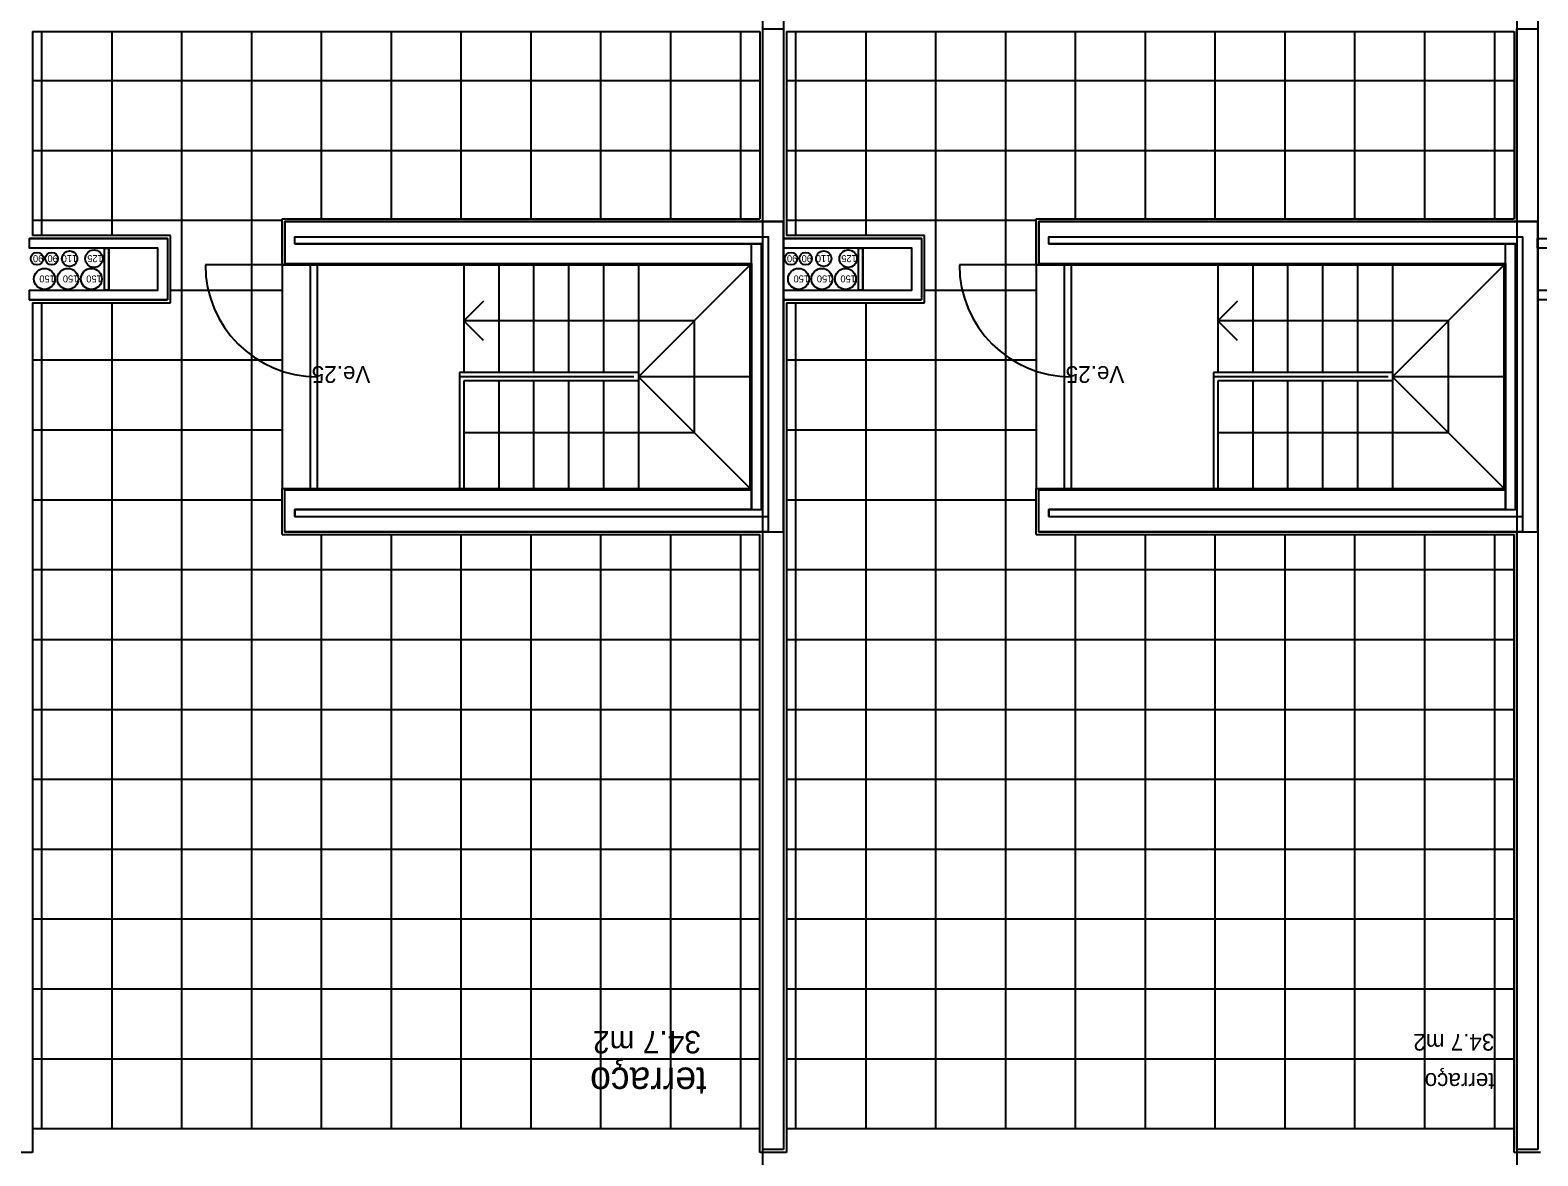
# Model space of a CAD drawing. Extents: x 1278 to 1356, y -253.7 to -224.
# Drawn here: x 1324.04 to 1334.83, y -246.8 to -238.74 of the extents above; entities that cross this region are included whole.
import ezdxf

# ---------------------------------------------------------------- set-up
doc = ezdxf.new("R2010")
doc.units = 0
for name, color, linetype in [('corte', 7, 'Continuous'), ('estereoctomias', 7, 'Continuous'), ('estrutura-eixos', 7, 'Continuous'), ('Level 1', 7, 'Continuous'), ('Level 13', 7, 'Continuous'), ('Level 2', 7, 'Continuous'), ('Level 21', 7, 'Continuous'), ('Level 40', 7, 'Continuous'), ('Level 41', 7, 'Continuous'), ('Level 60', 7, 'Continuous'), ('revestimentos', 7, 'Continuous')]:
    doc.layers.add(name, color=color, linetype=linetype)

msp = doc.modelspace()

# ---------------------------------------------------------------- linework, layer by layer
at = {"layer": 'corte'}
for p, q in [((1325.022, -240.234), (1324.034, -240.234)), ((1325.02, -240.234), (1325.02, -240.674)), ((1325.932, -240.224), (1329.322, -240.224)), ((1325.932, -240.274), (1325.932, -240.224)), ((1329.322, -240.224), (1329.322, -242.224)), ((1330.42, -240.234), (1329.432, -240.234)), ((1330.418, -240.234), (1330.418, -240.674)), ((1331.33, -240.224), (1334.721, -240.224)), ((1331.33, -240.274), (1331.33, -240.224)), ((1334.721, -240.224), (1334.721, -242.224)), ((1324.952, -240.304), (1324.032, -240.304)), ((1324.57, -240.604), (1324.57, -240.304)), ((1324.6, -240.604), (1324.6, -240.304)), ((1324.95, -240.304), (1324.95, -240.604)), ((1325.932, -240.274), (1329.273, -240.274)), ((1329.273, -240.274), (1329.273, -242.174)), ((1330.35, -240.304), (1329.43, -240.304)), ((1329.968, -240.604), (1329.968, -240.304)), ((1329.998, -240.604), (1329.998, -240.304)), ((1330.348, -240.304), (1330.348, -240.604)), ((1331.33, -240.274), (1334.671, -240.274)), ((1334.671, -240.274), (1334.671, -242.174)), ((1335.75, -240.304), (1334.83, -240.304)), ((1324.032, -240.604), (1324.952, -240.604)), ((1324.034, -240.674), (1325.022, -240.674)), ((1329.43, -240.604), (1330.35, -240.604)), ((1329.432, -240.674), (1330.42, -240.674)), ((1334.83, -240.604), (1335.75, -240.604))]:
    msp.add_line(p, q, dxfattribs=at)
at = {"layer": 'estereoctomias'}
for p, q in [((1324.122, -240.214), (1324.122, -238.754)), ((1329.52, -240.214), (1329.52, -238.754)), ((1324.122, -246.604), (1324.122, -240.694)), ((1329.52, -246.604), (1329.52, -240.694))]:
    msp.add_line(p, q, dxfattribs=at)
for points in [[(1329.432, -240.114), (1329.282, -240.114), (1329.282, -238.734), (1329.432, -238.734)], [(1334.831, -240.114), (1334.681, -240.114), (1334.681, -238.734), (1334.831, -238.734)], [(1329.432, -240.114), (1325.862, -240.114), (1325.862, -240.414), (1329.202, -240.414), (1329.202, -242.174), (1329.273, -242.174), (1329.273, -240.414), (1329.273, -240.284), (1329.273, -240.274), (1325.932, -240.274), (1325.932, -240.224), (1329.322, -240.224), (1329.322, -242.334), (1329.432, -242.334), (1329.432, -240.224)], [(1334.831, -240.114), (1331.26, -240.114), (1331.26, -240.414), (1334.6, -240.414), (1334.6, -242.174), (1334.671, -242.174), (1334.671, -240.414), (1334.671, -240.284), (1334.671, -240.274), (1331.33, -240.274), (1331.33, -240.224), (1334.721, -240.224), (1334.721, -242.334), (1334.831, -242.334), (1334.831, -240.224)], [(1325.022, -240.674), (1324.034, -240.674), (1324.034, -240.604), (1324.952, -240.604), (1324.952, -240.304), (1324.032, -240.304), (1324.032, -240.234), (1325.022, -240.234)], [(1330.42, -240.674), (1329.432, -240.674), (1329.432, -240.604), (1330.35, -240.604), (1330.35, -240.304), (1329.43, -240.304), (1329.43, -240.234), (1330.42, -240.234)], [(1335.82, -240.674), (1334.832, -240.674), (1334.832, -240.604), (1335.75, -240.604), (1335.75, -240.304), (1334.83, -240.304), (1334.83, -240.234), (1335.82, -240.234)], [(1324.6, -240.604), (1324.57, -240.604), (1324.57, -240.304), (1324.6, -240.304)], [(1329.998, -240.604), (1329.968, -240.604), (1329.968, -240.304), (1329.998, -240.304)], [(1329.322, -242.224), (1329.322, -242.334), (1325.862, -242.334), (1325.862, -242.034), (1329.202, -242.034), (1329.202, -242.174), (1325.932, -242.174), (1325.932, -242.224)], [(1334.721, -242.224), (1334.721, -242.334), (1331.26, -242.334), (1331.26, -242.034), (1334.6, -242.034), (1334.6, -242.174), (1331.33, -242.174), (1331.33, -242.224)], [(1329.432, -246.754), (1329.282, -246.754), (1329.282, -242.334), (1329.432, -242.334)], [(1334.831, -246.754), (1334.681, -246.754), (1334.681, -242.334), (1334.831, -242.334)]]:
    msp.add_lwpolyline(points, close=True, dxfattribs=at)
at = {"layer": 'estrutura-eixos'}
for p, q in [((1329.284, -250.792), (1329.284, -229.62)), ((1334.684, -250.792), (1334.684, -229.62))]:
    msp.add_line(p, q, dxfattribs=at)
at = {"layer": 'Level 1'}
for p, q in [((1329.432, -232.094), (1329.432, -246.754)), ((1334.831, -232.094), (1334.831, -246.754)), ((1329.282, -240.114), (1329.282, -238.734)), ((1334.681, -240.114), (1334.681, -238.734)), ((1325.862, -240.114), (1329.432, -240.114)), ((1325.862, -240.414), (1325.862, -240.114)), ((1331.26, -240.114), (1334.831, -240.114)), ((1331.26, -240.414), (1331.26, -240.114)), ((1329.202, -242.174), (1329.202, -240.274)), ((1334.6, -242.174), (1334.6, -240.274)), ((1325.862, -240.414), (1329.202, -240.414)), ((1331.26, -240.414), (1334.6, -240.414)), ((1325.862, -242.034), (1329.202, -242.034)), ((1325.862, -242.334), (1325.862, -242.034)), ((1331.26, -242.034), (1334.6, -242.034)), ((1331.26, -242.334), (1331.26, -242.034)), ((1325.932, -242.174), (1329.273, -242.174)), ((1325.932, -242.224), (1325.932, -242.174)), ((1331.33, -242.174), (1334.671, -242.174)), ((1331.33, -242.224), (1331.33, -242.174)), ((1325.932, -242.224), (1329.322, -242.224)), ((1331.33, -242.224), (1334.721, -242.224)), ((1325.862, -242.334), (1329.432, -242.334)), ((1329.282, -246.754), (1329.282, -242.334)), ((1331.26, -242.334), (1334.831, -242.334)), ((1334.681, -246.754), (1334.681, -242.334)), ((1329.432, -246.754), (1329.282, -246.754)), ((1334.831, -246.754), (1334.681, -246.754))]:
    msp.add_line(p, q, dxfattribs=at)
at = {"layer": 'Level 13'}
for p, q in [((1326.042, -240.424), (1325.292, -240.424)), ((1326.042, -240.424), (1326.042, -242.024)), ((1326.092, -240.424), (1326.092, -242.024)), ((1331.44, -240.424), (1330.69, -240.424)), ((1331.44, -240.424), (1331.44, -242.024)), ((1331.49, -240.424), (1331.49, -242.024))]:
    msp.add_line(p, q, dxfattribs=at)
for centre in [(1326.092, -240.424), (1331.49, -240.424)]:
    msp.add_arc(centre, 0.8, 180, 270, dxfattribs=at)
at = {"layer": 'Level 2'}
for p, q in [((1325.842, -240.424), (1325.842, -242.024)), ((1327.142, -240.424), (1327.142, -241.194)), ((1327.392, -240.424), (1327.392, -241.194)), ((1327.642, -240.424), (1327.642, -241.194)), ((1327.892, -240.424), (1327.892, -241.194)), ((1328.142, -240.424), (1328.142, -241.194)), ((1328.392, -240.424), (1328.392, -241.194)), ((1328.392, -241.224), (1329.192, -240.424)), ((1331.24, -240.424), (1331.24, -242.024)), ((1332.54, -240.424), (1332.54, -241.194)), ((1332.79, -240.424), (1332.79, -241.194)), ((1333.04, -240.424), (1333.04, -241.194)), ((1333.29, -240.424), (1333.29, -241.194)), ((1333.54, -240.424), (1333.54, -241.194)), ((1333.79, -240.424), (1333.79, -241.194)), ((1333.79, -241.224), (1334.59, -240.424)), ((1327.283, -240.683), (1327.142, -240.824)), ((1332.682, -240.683), (1332.54, -240.824)), ((1328.792, -240.824), (1327.142, -240.824)), ((1327.283, -240.965), (1327.142, -240.824)), ((1328.792, -240.824), (1328.792, -241.624)), ((1334.19, -240.824), (1332.54, -240.824)), ((1332.682, -240.965), (1332.54, -240.824)), ((1334.19, -240.824), (1334.19, -241.624)), ((1328.392, -241.194), (1327.112, -241.194)), ((1327.112, -241.194), (1327.112, -242.024)), ((1328.36, -241.224), (1327.112, -241.224)), ((1328.392, -241.194), (1328.392, -241.254)), ((1329.192, -241.224), (1328.392, -241.224)), ((1328.392, -241.224), (1329.192, -242.024)), ((1333.79, -241.194), (1332.51, -241.194)), ((1332.51, -241.194), (1332.51, -242.024)), ((1333.759, -241.224), (1332.51, -241.224)), ((1333.79, -241.194), (1333.79, -241.254)), ((1334.59, -241.224), (1333.79, -241.224)), ((1333.79, -241.224), (1334.59, -242.024)), ((1328.392, -241.254), (1327.142, -241.254)), ((1327.142, -241.254), (1327.142, -242.024)), ((1327.142, -241.254), (1327.142, -242.024)), ((1327.392, -241.254), (1327.392, -242.024)), ((1327.642, -241.254), (1327.642, -242.024)), ((1327.892, -241.254), (1327.892, -242.024)), ((1328.142, -241.254), (1328.142, -242.024)), ((1328.392, -241.254), (1328.392, -242.024)), ((1333.79, -241.254), (1332.54, -241.254)), ((1332.54, -241.254), (1332.54, -242.024)), ((1332.54, -241.254), (1332.54, -242.024)), ((1332.79, -241.254), (1332.79, -242.024)), ((1333.04, -241.254), (1333.04, -242.024)), ((1333.29, -241.254), (1333.29, -242.024)), ((1333.54, -241.254), (1333.54, -242.024)), ((1333.79, -241.254), (1333.79, -242.024)), ((1327.142, -241.624), (1328.792, -241.624)), ((1332.54, -241.624), (1334.19, -241.624)), ((1324.054, -246.604), (1329.262, -246.604)), ((1329.452, -246.604), (1334.661, -246.604))]:
    msp.add_line(p, q, dxfattribs=at)
at = {"layer": 'Level 21'}
for p, q in [((1324.622, -238.754), (1324.622, -240.214)), ((1325.122, -238.754), (1325.122, -246.604)), ((1325.622, -238.754), (1325.622, -246.604)), ((1326.122, -238.754), (1326.122, -240.094)), ((1326.622, -238.754), (1326.622, -240.094)), ((1327.122, -238.754), (1327.122, -240.094)), ((1327.622, -238.754), (1327.622, -240.094)), ((1328.122, -238.754), (1328.122, -240.094)), ((1328.622, -238.754), (1328.622, -240.094)), ((1329.122, -238.754), (1329.122, -240.094)), ((1330.02, -238.754), (1330.02, -240.214)), ((1330.52, -238.754), (1330.52, -246.604)), ((1331.02, -238.754), (1331.02, -246.604)), ((1331.52, -238.754), (1331.52, -240.094)), ((1332.02, -238.754), (1332.02, -240.094)), ((1332.52, -238.754), (1332.52, -240.094)), ((1333.02, -238.754), (1333.02, -240.094)), ((1333.52, -238.754), (1333.52, -240.094)), ((1334.02, -238.754), (1334.02, -240.094)), ((1334.52, -238.754), (1334.52, -240.094)), ((1324.054, -239.104), (1329.262, -239.104)), ((1329.452, -239.104), (1334.661, -239.104)), ((1324.054, -239.604), (1329.262, -239.604)), ((1329.452, -239.604), (1334.661, -239.604)), ((1324.054, -240.104), (1325.842, -240.104)), ((1329.452, -240.104), (1331.24, -240.104)), ((1324.622, -240.694), (1324.622, -246.604)), ((1325.04, -240.604), (1325.842, -240.604)), ((1330.02, -240.694), (1330.02, -246.604)), ((1330.438, -240.604), (1331.24, -240.604)), ((1324.054, -241.104), (1325.842, -241.104)), ((1329.452, -241.104), (1331.24, -241.104)), ((1324.054, -241.604), (1325.842, -241.604)), ((1329.452, -241.604), (1331.24, -241.604)), ((1324.054, -242.104), (1325.842, -242.104)), ((1329.452, -242.104), (1331.24, -242.104)), ((1326.122, -242.354), (1326.122, -246.604)), ((1326.622, -242.354), (1326.622, -246.604)), ((1327.122, -242.354), (1327.122, -246.604)), ((1327.622, -242.354), (1327.622, -246.604)), ((1328.122, -242.354), (1328.122, -246.604)), ((1328.622, -242.354), (1328.622, -246.604)), ((1329.122, -242.354), (1329.122, -246.604)), ((1331.52, -242.354), (1331.52, -246.604)), ((1332.02, -242.354), (1332.02, -246.604)), ((1332.52, -242.354), (1332.52, -246.604)), ((1333.02, -242.354), (1333.02, -246.604)), ((1333.52, -242.354), (1333.52, -246.604)), ((1334.02, -242.354), (1334.02, -246.604)), ((1334.52, -242.354), (1334.52, -246.604)), ((1324.054, -242.604), (1329.262, -242.604)), ((1329.452, -242.604), (1334.661, -242.604)), ((1324.054, -243.104), (1329.262, -243.104)), ((1329.452, -243.104), (1334.661, -243.104)), ((1324.054, -243.604), (1329.262, -243.604)), ((1329.452, -243.604), (1334.661, -243.604)), ((1324.054, -244.104), (1329.262, -244.104)), ((1329.452, -244.104), (1334.661, -244.104)), ((1324.054, -244.604), (1329.262, -244.604)), ((1329.452, -244.604), (1334.661, -244.604)), ((1324.054, -245.104), (1329.262, -245.104)), ((1329.452, -245.104), (1334.661, -245.104)), ((1324.054, -245.604), (1329.262, -245.604)), ((1329.452, -245.604), (1334.661, -245.604)), ((1324.054, -246.104), (1329.262, -246.104)), ((1329.452, -246.104), (1334.661, -246.104))]:
    msp.add_line(p, q, dxfattribs=at)
at = {"layer": 'Level 41'}
for centre, radius in [((1324.087, -240.379), 0.045), ((1324.191, -240.379), 0.045), ((1324.32, -240.379), 0.055), ((1324.495, -240.379), 0.0625), ((1329.485, -240.379), 0.045), ((1329.59, -240.379), 0.045), ((1329.719, -240.379), 0.055), ((1329.894, -240.379), 0.0625), ((1324.14, -240.524), 0.075), ((1324.308, -240.524), 0.075), ((1324.476, -240.524), 0.075), ((1329.539, -240.524), 0.075), ((1329.706, -240.524), 0.075), ((1329.875, -240.524), 0.075)]:
    msp.add_circle(centre, radius, dxfattribs=at)
at = {"layer": 'revestimentos'}
for p, q in [((1324.054, -238.754), (1324.054, -240.214)), ((1324.054, -238.754), (1329.262, -238.754)), ((1329.262, -238.754), (1329.262, -240.094)), ((1329.452, -238.754), (1329.452, -240.214)), ((1329.452, -238.754), (1334.661, -238.754)), ((1334.661, -238.754), (1334.661, -240.094)), ((1325.842, -240.424), (1325.842, -240.094)), ((1325.842, -240.094), (1329.262, -240.094)), ((1331.24, -240.424), (1331.24, -240.094)), ((1331.24, -240.094), (1334.661, -240.094)), ((1325.042, -240.214), (1324.054, -240.214)), ((1325.04, -240.214), (1325.04, -240.694)), ((1330.44, -240.214), (1329.452, -240.214)), ((1330.438, -240.214), (1330.438, -240.694)), ((1325.842, -240.424), (1329.192, -240.424)), ((1329.192, -242.024), (1329.192, -240.424)), ((1331.24, -240.424), (1334.59, -240.424)), ((1334.59, -242.024), (1334.59, -240.424)), ((1324.054, -240.694), (1324.054, -246.774)), ((1324.054, -240.694), (1325.042, -240.694)), ((1329.452, -240.694), (1329.452, -246.774)), ((1329.452, -240.694), (1330.44, -240.694)), ((1325.842, -242.354), (1325.842, -242.024)), ((1325.842, -242.024), (1329.192, -242.024)), ((1331.24, -242.354), (1331.24, -242.024)), ((1331.24, -242.024), (1334.59, -242.024)), ((1325.842, -242.354), (1329.262, -242.354)), ((1329.262, -246.774), (1329.262, -242.354)), ((1331.24, -242.354), (1334.661, -242.354)), ((1334.661, -246.774), (1334.661, -242.354)), ((1324.054, -246.774), (1323.864, -246.774)), ((1329.452, -246.774), (1329.262, -246.774)), ((1334.851, -246.774), (1334.661, -246.774))]:
    msp.add_line(p, q, dxfattribs=at)

# ---------------------------------------------------------------- texts
at = {"layer": 'Level 40'}
for p in [(1326.473, -241.148), (1331.871, -241.148)]:
    msp.add_text('Ve.25', height=0.12, rotation=180, dxfattribs=at).set_placement(p)
at = {"layer": 'Level 41'}
for s, p in [('90', (1324.132, -240.354)), ('90', (1324.236, -240.354)), ('110', (1324.375, -240.354)), ('125', (1324.558, -240.354)), ('90', (1329.53, -240.354)), ('90', (1329.635, -240.354)), ('110', (1329.774, -240.354)), ('125', (1329.956, -240.354)), ('150', (1324.215, -240.499)), ('150', (1324.383, -240.499)), ('150', (1324.551, -240.499)), ('150', (1329.614, -240.499)), ('150', (1329.781, -240.499)), ('150', (1329.95, -240.499))]:
    msp.add_text(s, height=0.05, rotation=180, dxfattribs=at).set_placement(p)
at = {"layer": 'Level 60'}
for s, height, p in [('34.7 m2', 0.16, (1328.84, -245.906)), ('34.7 m2', 0.12, (1334.52, -245.926)), ('terraço', 0.2, (1328.879, -246.167)), ('terraço', 0.12, (1334.521, -246.207))]:
    msp.add_text(s, height=height, rotation=180, dxfattribs=at).set_placement(p)

doc.saveas('drawing.dxf')
